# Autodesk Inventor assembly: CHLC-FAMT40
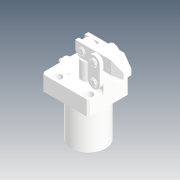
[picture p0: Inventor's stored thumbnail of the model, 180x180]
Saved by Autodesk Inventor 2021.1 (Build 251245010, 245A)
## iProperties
Created: 2019-04
Part Number: CHLC-FAMT40
Description: STEP AP214
Document SubType Name: Assembly
Designer: user
Title: CHLC-FAMT40.STEP
Revision Number: ÈÎºÎ
Sending System: SolidWorks 2016
Preprocessor: SwSTEP 2.0
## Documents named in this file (10)
- D:\Vault_2016\Projekty\Clamptek\Hydraulic\CHLC\CHLC-40\Inventor\CHLC-FAMT40\CHLC-FAMT40.iam
- D:\Vault_2016\Projekty\Clamptek\Hydraulic\CHLC\CHLC-40\Inventor\CHLC-FAMT40\CHLC-40-01.ipt
- D:\Vault_2016\Projekty\Clamptek\Hydraulic\CHLC\CHLC-40\Inventor\CHLC-FAMT40\CHLC-40-03.ipt
- D:\Vault_2016\Projekty\Clamptek\Hydraulic\CHLC\CHLC-40\Inventor\CHLC-FAMT40\CHLC-40-06.ipt
- D:\Vault_2016\Projekty\Clamptek\Hydraulic\CHLC\CHLC-40\Inventor\CHLC-FAMT40\CHLC-40-04.ipt
- D:\Vault_2016\Projekty\Clamptek\Hydraulic\CHLC\CHLC-40\Inventor\CHLC-FAMT40\CHLC-40-08.ipt
- D:\Vault_2016\Projekty\Clamptek\Hydraulic\CHLC\CHLC-40\Inventor\CHLC-FAMT40\CHLC-40-02.ipt
- D:\Vault_2016\Projekty\Clamptek\Hydraulic\CHLC\CHLC-40\Inventor\CHLC-FAMT40\M6LS.ipt
- D:\Vault_2016\Projekty\Clamptek\Hydraulic\CHLC\CHLC-40\Inventor\CHLC-FAMT40\CHLC-FAMT40-BT.ipt
- D:\Vault_2016\Projekty\Clamptek\Hydraulic\CHLC\CHLC-40\Inventor\CHLC-FAMT40\CZL20µ÷ËÙ·§.iam
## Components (18 placed, 18 different names)
1. CHLC-40-01_1
2. CHLC-40-03_2
3. CHLC-40-06_3
4. CHLC-40-04_4
5. CHLC-40-08_5
6. CHLC-40-03_6
7. CHLC-40-02_7
8. M6LS_8
9. CHLC-40-06_9
10. CHLC-40-06_10
11. CHLC-40-06_11
12. CHLC-40-06_12
13. CHLC-40-06_13
14. CHLC-40-02_14
15. M6LS_15
16. M6LS_16
17. CHLC-FAMT40-BT_17
18. CZL20µ÷ËÙ·§_18 [sub-assembly]
